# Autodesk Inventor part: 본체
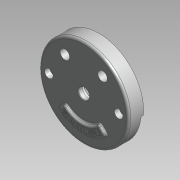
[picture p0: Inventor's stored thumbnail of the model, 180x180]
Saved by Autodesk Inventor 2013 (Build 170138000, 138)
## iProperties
Created: 2015-04
Part Number: 본체
Material: 알루미늄 6061
Document SubType Name: 모델링
Designer: Administrator
Mass: 1051.47 g
Surface Area: 1036.79 cm^2
Volume: 387.998 cm^3
Density: 2.71 g/cm^3
Author: Administrator
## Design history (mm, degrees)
sketch "스케치2"
  geometry: C1 r 95 at (0, 0); 1 further point
  constraints: 1 centre point, 1 coincident
  dimensions: "d0" = 190 diameter of C1
extrude "돌출1" new body sketch "스케치2" distance "d1" = 32; taper "d2" = 0 deg
sketch "스케치3"
  geometry: C1 r 95 at (0, 0) reference; C2 r 90 at (0, 0)
  constraints: 1 centre point, 1 coincident
  dimensions: "d3" = 180 diameter of C2
extrude "돌출2" cut sketch "스케치3" distance "d4" = 18; taper "d5" = 0 deg
sketch "스케치5"
  geometry: C1 r 90 at (0, 0) reference; C2 r 35 at (0, 0)
  constraints: 1 centre point, 1 coincident
  dimensions: "d8" = 70 diameter of C2
extrude "돌출3" join sketch "스케치5" distance "d9" = 10; taper "d10" = -10 deg
hole "구멍1" diameter "d13" = 23; stored, may be unused: countersink angle "d17" = 90 deg, drill point angle "d19" = 118 deg; dims "d11" = 10, "d12" = 10, "d14" = 6, "d15" = 50, "d16" = 15, "d18" = 8
sketch "스케치6"
  geometry: L1 (-59, -19)-(59, -19); L2 (-59, -19)-(-59, -14); L3 (-41, -19)-(-41, -14); L4 (41, -19)-(41, -14); L5 (59, -19)-(59, -14); A1 r 41 centre (0, -19) between (-41, -19) and (41, -19); A2 r 59 centre (0, -19) between (-59, -19) and (59, -19); A3 r 9 centre (-50, -14) between (-41, -14) and (-59, -14); A4 r 9 centre (50, -14) between (59, -14) and (41, -14); 1 further point
  constraints: 10 end point, 8 point on circle, 4 centre point, 4 tangent, 3 parallel, 2 point on line, 1 coincident, 1 horizontal, 1 perpendicular
  dimensions: "d22" = 82 diameter of A1; "d27" = 5 distance of L4.end L4.start; "d140" = 19 distance from line of L1 point (0, 0)
sketch "스케치8"
  geometry: L1 (-89.658, -7.844)-(-94.638, -8.28); L2 (0, 0)-(114.484, 0); L3 (89.658, -7.844)-(94.638, -8.28); L4 (0, 0)-(108.89, 0); A1 r 90 centre (0, 0) between (-89.658, -7.844) and (89.658, -7.844) reference; A2 r 95 centre (0, 0) between (-94.638, -8.28) and (94.638, -8.28) reference
  constraints: 8 end point, 4 point on circle, 2 horizontal
  dimensions: "d33" = 175 deg angle of L1 L2; "d34" = 5 deg angle of L3 L4
extrude "돌출6" cut sketch "스케치8" distance "d35" = 5; taper "d36" = 0 deg
extrude "돌출8" cut sketch "스케치6" distance "d39" = 7; taper "d40" = 0 deg
sketch "스케치9"
  geometry: L1 (41, -19)-(41, -14) reference; L2 (-89.196, 12)-(-40.249, 12); L3 (40.249, 12)-(89.196, 12); C1 r 35 at (0, 0) reference; A1 r 90 centre (0, 0) between (-89.196, 12) and (89.196, 12) reference; A2 r 42 centre (0, 0) between (40.249, 12) and (-40.249, 12)
  constraints: 4 end point, 4 point on circle, 1 centre point, 1 coincident, 1 collinear, 1 perpendicular
  dimensions: "d42" = 12 distance from line of A2.centre L2; "d43" = 12 distance from line of C1.centre L3
extrude "돌출9" cut sketch "스케치9" distance "d44" = 7; taper "d45" = 0 deg
sketch "스케치11"
  geometry: C1 r 11.5 at (0, 0) reference; 2 further points
  constraints: 2 horizontal alignment
  dimensions: "d46" = 148 distance of point (74, 0) point (-74, 0); "d48" = 74 distance of point (-74, 0) C1.centre (= 0.5 x d46)
hole "구멍2" sketch "스케치11" at (-74, 0), (74, 0) diameter "d49" = 11; stored, may be unused: countersink angle "d53" = 90 deg, drill point angle "d55" = 118 deg; dims "d50" = 6, "d51" = 18, "d52" = 11, "d54" = 8
sketch "스케치12"
  geometry: C1 r 15 at (-40, 52); C2 r 15 at (40, 52); A1 r 42 centre (0, 0) between (40.249, 12) and (-40.249, 12) reference
  constraints: 2 centre point
  dimensions: "d56" = 30 diameter of C1; "d57" = 30 diameter of C2; "d58" = 80 distance of C1.centre C2.centre; "d59" = 40 horizontal distance of A1.centre C1.centre (= 0.5 x d58); "d60" = 52 vertical distance of A1.centre C2.centre; "d61" = 52 vertical distance of A1.centre C1.centre
extrude "돌출10" join sketch "스케치12" distance "d62" = 25; taper "d63" = 0 deg
hole "구멍3" diameter "d66" = 20; stored, may be unused: countersink angle "d70" = 90 deg, drill point angle "d72" = 118 deg; dims "d64" = 10, "d65" = 10, "d67" = 6, "d68" = 18, "d69" = 11, "d71" = 8
hole "구멍4" diameter "d75" = 20; stored, may be unused: countersink angle "d79" = 90 deg, drill point angle "d81" = 118 deg; dims "d73" = 10, "d74" = 10, "d76" = 6, "d77" = 18, "d78" = 11, "d80" = 8
sketch "스케치14"
  geometry: L1 (-6, -17.697)-(-6, 19.707); L2 (6, 19.707)-(6, -17.697); L3 (6, 19.707)-(-6, 19.707); L4 (6, -17.697)-(-6, -17.697); C1 r 10 at (0, 0) reference; 1 further point
  constraints: 8 end point, 2 parallel, 1 perpendicular, 1 vertical
  dimensions: "d82" = 12 distance between parallel lines of L2 L1; "d84" = 6 distance from line of L1 C1.centre (= 0.5 x d82)
extrude "돌출11" cut sketch "스케치14" distance "d85" = 3; taper "d86" = 0 deg
sketch "스케치15"
  geometry: L1 (-23.35, 6)-(20.051, 6); L2 (-23.35, -6)-(20.051, -6); L3 (20.051, -6)-(20.051, 6); L4 (-23.35, -6)-(-23.35, 6); C1 r 10 at (0, 0) reference; 1 further point
  constraints: 8 end point, 2 perpendicular, 1 horizontal, 1 parallel
  dimensions: "d87" = 6 distance from line of L1 C1.centre (= 0.5 x d88); "d88" = 12 distance between parallel lines of L2 L1
extrude "돌출12" cut sketch "스케치15" distance "d89" = 3; taper "d90" = 0 deg
sketch "스케치16"
  geometry: C1 r 5.5 at (74, 0) reference; C2 r 5.5 at (-74, 0) reference; C3 r 9 at (-74, 0); C4 r 9 at (74, 0)
  constraints: 2 centre point, 2 coincident
  dimensions: "d91" = 18 diameter of C3; "d92" = 18 diameter of C4
extrude "돌출13" join sketch "스케치16" distance "d93" = 18; taper "d94" = 0 deg
fillet "모깎기1" dims "d95" = 10
fillet "모깎기2" dims "d96" = 10
fillet "모깎기3" dims "d97" = 3
fillet "모깎기4" dims "d98" = 3
chamfer "모따기1" distance "d99" = 1; stored, may be unused: second distance "d100" = 2, angle "d101" = 45 deg
chamfer "모따기2" distance "d102" = 1; stored, may be unused: second distance "d103" = 2, angle "d104" = 45 deg
chamfer "모따기3" distance "d105" = 1; stored, may be unused: second distance "d106" = 2, angle "d107" = 45 deg
fillet "모깎기5" dims "d108" = 3
fillet "모깎기6" dims "d109" = 3
sketch "스케치17"
  geometry: L1 (0, 0)-(117.38, 0); L2 (0, 0)-(130.203, 0); L3 (-36.062, -36.062)-(-50.912, -50.912); L4 (36.062, -36.062)-(50.912, -50.912); C1 r 12.5 at (0, 0) reference; A1 r 51 centre (0, 0) between (-36.062, -36.062) and (36.062, -36.062); A2 r 72 centre (0, 0) between (-50.912, -50.912) and (50.912, -50.912)
  constraints: 8 end point, 4 point on circle, 2 centre point, 2 coincident, 2 horizontal
  dimensions: "d110" = 102 diameter of A1; "d114" = 72 radius of A2
extrude "돌출14" join sketch "스케치17" distance "d116" = 5; taper "d117" = 0 deg
fillet "모깎기7" dims "d118" = 5
fillet "모깎기10" dims "d124" = 3
fillet "모깎기11" dims "d125" = 5
sketch "스케치21"
  geometry: L1 (0, 0)-(85.902, 0); L2 (-1.365, -1.365)-(92.871, -1.365); A1 r 68 centre (0, 0) between (67.986, -1.365) and (68, 0); A2 r 68 centre (0, 0) between (-48.083, -48.083) and (48.083, -48.083); 1 further point
  constraints: 4 end point, 4 point on circle, 2 centre point, 2 horizontal, 2 point on line, 1 coincident, 1 other
feature "엠보싱2" sketch "스케치21" dims "d0" = 190, "d133" = 0.5, "d134" = 0
fillet "모깎기12" dims "d135" = 3
fillet "모깎기13" dims "d136" = 0.3
fillet "모깎기14" dims "d137" = 1
fillet "모깎기15" dims "d141" = 3
fillet "모깎기16" dims "d142" = 5
node "솔리드1"
node "솔리드 본체"
node "곡면 본체"
other parameters: "d41" = 84, "d111" = 144, "d112" = 135 deg, "d113" = 45 deg, "d128" = 136, "d130" = 136
